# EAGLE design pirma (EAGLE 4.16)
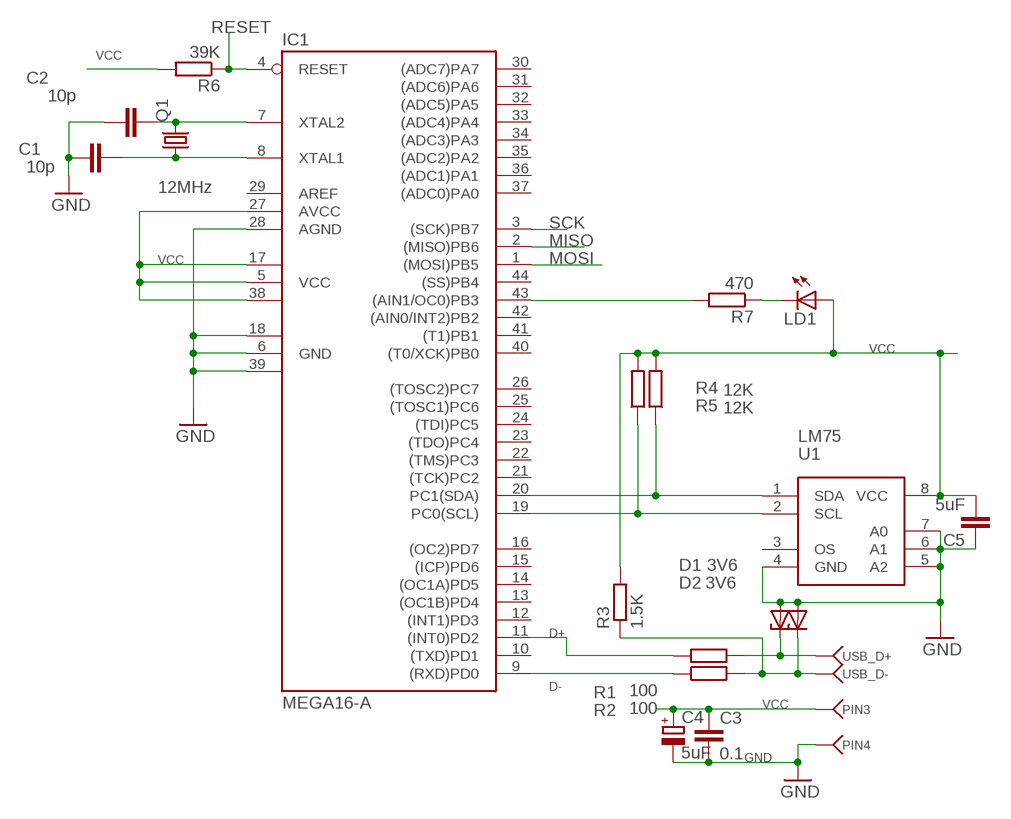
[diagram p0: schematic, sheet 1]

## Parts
C1  10p  C-EUC0603K  [C0603K]
C2  10p  C-EUC0603K  [C0603K]
C3  0.1  C-EUC3225  [C3225]
C4  5uF  CPOL-EUB/3528-21R  [B/3528-21R]
C5  5uF  C-EUC0603K  [C0603K]
D1  3V6  ZENER-DIODESOD80C  [SOD80C]
D2  3V6  ZENER-DIODESOD80C  [SOD80C]
IC1  MEGA16-A  [TQFP44]
LD1  LEDCHIPLED_1206  [CHIPLED_1206]
PIN3  PINSMD  [PIN-T]
PIN4  PINSMD  [PIN-T]
Q1  12MHz  CRYTALHC49S  [HC49/S]
R1  100  R-EU_M0805  [M0805]
R2  100  R-EU_M0805  [M0805]
R3  1.5K  R-EU_M0805  [M0805]
R4  12K  R-EU_M0805  [M0805]
R5  12K  R-EU_M0805  [M0805]
R6  39K  R-EU_M0805  [M0805]
R7  470  R-EU_M0805  [M0805]
U1  LM75  [SO08]
USB_D+  PINSMD  [PIN-T]
USB_D-  PINSMD  [PIN-T]

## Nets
D+: D1.C R1.2 USB_D+.P$1(P)
D-: D2.C R2.2 R3.1 USB_D-.P$1(P)
GND: C1.1 C2.1 C3.2 C4.- C5.1 D1.A D2.A IC1.6(GND) IC1.18(GND1) IC1.28(AGND) IC1.39(GND2) PIN4.P$1(P) U1.4(GND) U1.5(A2) U1.6(A1) U1.7(A0)
MISO: IC1.2((MISO)PB6)
MOSI: IC1.1((MOSI)PB5)
N$1: IC1.9((RXD)PD0) R2.1
N$2: IC1.11((INT0)PD2) R1.1
N$3: C2.2 IC1.7(XTAL2) Q1.2
N$4: C1.2 IC1.8(XTAL1) Q1.1
N$7: IC1.20(PC1(SDA)) R5.1 U1.1(SDA)
N$8: IC1.19(PC0(SCL)) R4.1 U1.2(SCL)
N$10: IC1.43((AIN1/OC0)PB3) R7.2
N$11: LD1.C R7.1
RESET: IC1.4(RESET) R6.1
SCK: IC1.3((SCK)PB7)
VCC: C3.1 C4.+ C5.2 IC1.5(VCC) IC1.17(VCC1) IC1.27(AVCC) IC1.38(VCC2) LD1.A PIN3.P$1(P) R3.2 R4.2 R5.2 R6.2 U1.8(VCC)
Unconnected: IC1.10((TXD)PD1) IC1.12((INT1)PD3) IC1.13((OC1B)PD4) IC1.14((OC1A)PD5) IC1.15((ICP)PD6) IC1.16((OC2)PD7) IC1.21((TCK)PC2) IC1.22((TMS)PC3) IC1.23((TDO)PC4) IC1.24((TDI)PC5) IC1.25((TOSC1)PC6) IC1.26((TOSC2)PC7) IC1.30((ADC7)PA7) IC1.31((ADC6)PA6) IC1.32((ADC5)PA5) IC1.33((ADC4)PA4) IC1.34((ADC3)PA3) IC1.35((ADC2)PA2) IC1.36((ADC1)PA1) IC1.37((ADC0)PA0) IC1.40((T0/XCK)PB0) IC1.41((T1)PB1) IC1.42((AIN0/INT2)PB2) IC1.44((SS)PB4) U1.3(OS)

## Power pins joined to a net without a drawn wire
AREF: IC1.29(AREF)

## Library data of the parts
C1-C3 C5 = rcl:C-EU: CAPACITOR, European symbol
C4 = rcl:CPOL-EU: POLARIZED CAPACITOR, European symbol
D1 D2 = diode:ZENER-DIODE: Z-Diode
IC1 = atmel:MEGA16: MICROCONTROLLER 16 Kbytes FLASH 1 kbytes SRAM 512 bytes EEPROM USART 8-channel 10 bit ADC Source: avr.lbr
LD1 = led:LED: LED
PIN3 PIN4 USB_D+ USB_D- = LevoROMS:PIN*: PIN
Q1 = crystal:CRYTAL: CRYSTAL
R1-R7 = rcl:R-EU_: RESISTOR, European symbol
U1 = LevoROMS:LM75

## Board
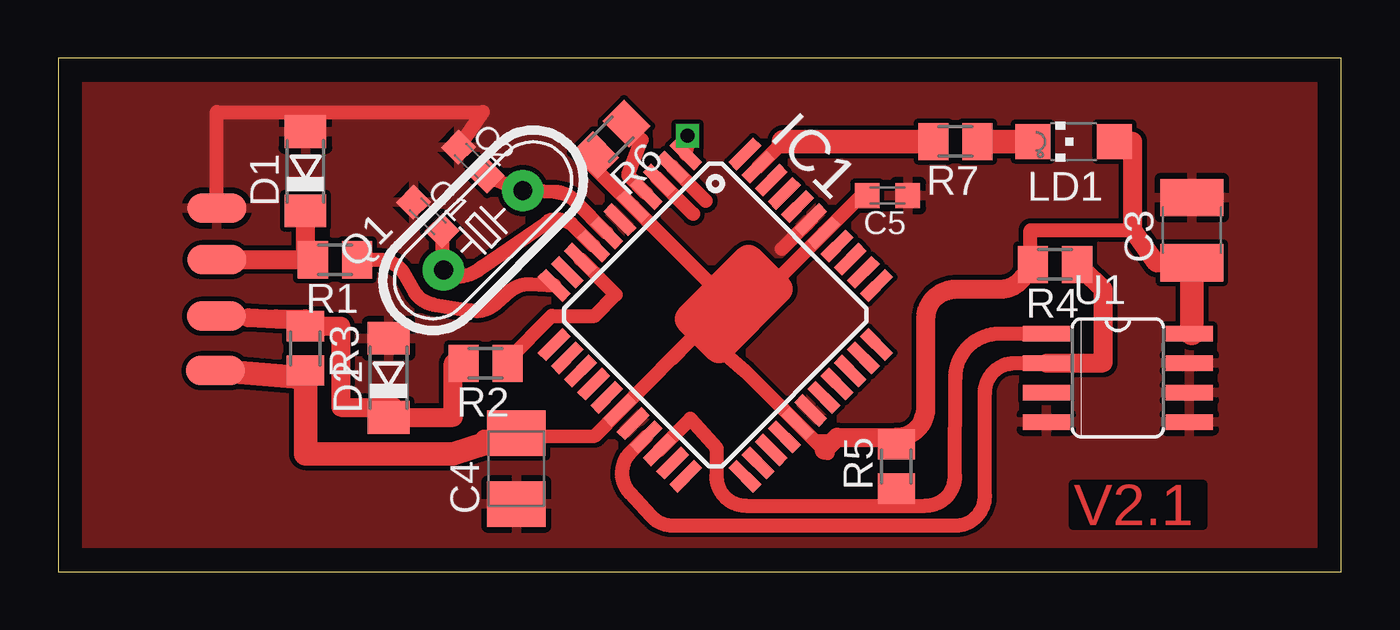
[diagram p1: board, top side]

Size 55.16 x 22.08 mm. Coordinates in mm from the lower left corner, seen from the top.
Outline: 0,0 55.16,0 55.16,22.08 0,22.08 0,0
Copper layers (1*16): Top 0.035mm / dielectric 1.5mm / Bottom 0.035mm
Design rules "default": minimum track width 10mil, minimum drill 24mil, track to track 8mil, track to pad 8mil, pad to pad 8mil, via to via 8mil, smd to smd 8mil, copper to edge 40mil, drill to drill 8mil, minimum pad ring 10mil, minimum via ring 8mil, stop-mask expansion 4mil, vias tented up to drill 0mil, thermal gap 10mil

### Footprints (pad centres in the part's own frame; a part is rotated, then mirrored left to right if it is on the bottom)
C0603K = smd 1.05 x 1.08: 1 -0.875,0; 2 0.875,0
C3225 = smd 1.6 x 2.7: 1 -1.4,0; 2 1.4,0
B/3528-21R = smd 1.95 x 2.5: + 1.525,0; - -1.525,0
SOD80C = smd 1.4 x 1.8: A 1.7,0; C -1.7,0
TQFP44 = smd 1.5 x 0.5: 1 -5.8,4; 2 -5.8,3.2; 3 -5.8,2.4; 4 -5.8,1.6; 5 -5.8,0.8; 6 -5.8,0; 7 -5.8,-0.8; 8 -5.8,-1.6; 9 -5.8,-2.4; 10 -5.8,-3.2; 11 -5.8,-4; 23 5.8,-4; 24 5.8,-3.2; 25 5.8,-2.4; 26 5.8,-1.6; 27 5.8,-0.8; 28 5.8,0; 29 5.8,0.8; 30 5.8,1.6; 31 5.8,2.4; 32 5.8,3.2; 33 5.8,4 | smd 0.5 x 1.5: 12 -4,-5.8; 13 -3.2,-5.8; 14 -2.4,-5.8; 15 -1.6,-5.8; 16 -0.8,-5.8; 17 0,-5.8; 18 0.8,-5.8; 19 1.6,-5.8; 20 2.4,-5.8; 21 3.2,-5.8; 22 4,-5.8; 34 4,5.8; 35 3.2,5.8; 36 2.4,5.8; 37 1.6,5.8; 38 0.8,5.8; 39 0,5.8; 40 -0.8,5.8; 41 -1.6,5.8; 42 -2.4,5.8; 43 -3.2,5.8; 44 -4,5.8
CHIPLED_1206 = smd 1.5 x 1.5: A 0,-1.75; C 0,1.75
PIN-T = smd 2.54 x 1.27: P$1 0,0
HC49/S = drill 0.813 pad 1.778 round: 1 -2.413,0; 2 2.413,0
M0805 = smd 1.3 x 1.6: 1 -0.95,0; 2 0.95,0
SO08 = smd 0.66 x 2.032: 1 -1.905,-3.073; 2 -0.635,-3.073; 3 0.635,-3.073; 4 1.905,-3.073; 5 1.905,3.073; 6 0.635,3.073; 7 -0.635,3.073; 8 -1.905,3.073

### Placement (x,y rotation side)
C1  15.89,15.27 315 top
C2  17.83,17.63 315 top
C3  48.73,14.68 90 top
C4  19.7,4.43 90 top
C5  35.65,16.17 180 top
D1  10.63,17.22 90 top
D2  14.21,8.33 90 top
IC1  28.25,11.03 315 top
LD1  43.65,18.49 90 top
PIN3  6.77,8.64 0 top
PIN4  6.82,15.63 0 top
Q1  18.27,14.68 45 top
R1  11.9,13.41 180 top
R2  18.37,8.95 180 top
R3  10.63,9.6 270 top
R4  42.85,13.21 180 top
R5  36.03,4.52 90 top
R6  23.76,18.59 225 top
R7  38.57,18.49 180 top
U1  45.55,8.33 270 top
USB_D+  6.82,13.41 0 top
USB_D-  6.8,10.99 0 top

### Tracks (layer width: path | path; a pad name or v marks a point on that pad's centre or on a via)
D+
  Top 0.61: R1.2 10.63,13.41
  Top 0.813: USB_D+.P$1 R1.2 | 10.63,13.41 D1.C
D-
  Top 0.61: USB_D-.P$1 8.18,10.92 | 10.63,10.87 R3.1
  Top 0.813: 8.18,10.92 9.36,10.87 10.63,10.87 | R3.1 12.15,10.55 12.15,7.06 14.44,7.06 14.44,6.63 D2.C 16.98,6.63 16.98,8.95 R2.2
GND
  Top 0.61: C2.1 18.25,19.76 6.82,19.76 PIN4.P$1 | 31.11,13.87 32.19,14.96 32.37,15.16 IC1.39
  pour Top: -2.07,23.57 -2.07,-0.56 57.62,-0.56 57.62,23.57
MISO
  Top 0.305: IC1.2 26.4,17.41 26.39,17.42
  Top 0.61: 27.85,15.94 26.39,17.42
MOSI  (via drill 0.6)
  Top 0.61: v27.05,18.74 27.14,18.49 IC1.1
N$1
  Top 0.61: IC1.9 23.97,11.91 23.07,11 21.22,11 19.38,9.14 R2.1
N$2
  Top 0.61: IC1.11 20.32,12.36 arc45 19.4,12.05 18.82,11.53 arc-53 17.72,11.23 16.1,11.49 arc-42 15.33,11.99 14.82,12.89 arc54 13.8,13.41 R1.1 13.17,13.41
N$3
  Top 0.61: IC1.7 22.19,15.96 arc43 21.35,16.33 19.95,16.4 Q1.2 19.94,16.38 C2.2
N$4
  Top 0.254: 20.99,14.99 21.13,15.1 arc-45 20.99,14.96 20.99,14.99 | 21.1,15.07 arc47 20.99,15.23 20.99,14.99
  Top 0.61: 16.58,13.01 16.77,12.78 17,12.69 arc45 18.2,13.08 20.99,14.99 | Q1.1 16.58,13.01 | 16.58,13.01 C1.2 | IC1.8 22.05,14.97 arc41 21.17,15.12 arc4 21.1,15.07
N$7
  Top 0.305: 36.03,2.83 R5.1
  Top 0.61: IC1.20 27.18,6.57 28.31,5.3 28.29,5.28 28.29,4.1 arc90 29.56,2.83 36.03,2.83 37.29,2.83 arc90 38.56,4.11 38.57,8.33 | 38.57,8.33 38.56,8.34 | 38.57,8.33 arc-90 40.48,10.24 U1.1
N$8
  Top 0.61: IC1.19 24.62,5.14 arc88 24.58,3.38 25.49,2.39 arc47 26.43,1.98 38.57,1.98 arc90 39.84,3.25 39.84,7.69 arc-90 41.11,8.96 U1.2
  Top 0.813: R4.1 44.92,12.14 44.92,9.6 44.92,8.98 U1.2
N$10
  Top 0.61: IC1.43 31.18,18.49
  Top 1.016: 31.18,18.49 R7.2
N$11
  Top 1.016: R7.1 LD1.C
RESET
  Top 0.61: IC1.4 24.51,17.04 25.08,18.56 24.44,19.2 R6.1
SCK
  Top 0.305: IC1.3 25.73,16.93
  Top 0.61: 25.73,16.93 27.29,15.37
VCC
  Top 0.254: R4.2 42.38,13.41 | C5.2 34.76,15.95 | 32.93,5.23 33.49,5.79 32.22,5.79 32.29,5.86 | 30.95,12.14 30.66,12.32
  Top 0.61: 26.41,9.17 27.68,10.46 IC1.17 23.07,5.84 18.25,5.79 C4.+ | 28.41,9.6 29.52,8.62 IC1.27 32.29,5.86 33.07,5.09 | 30.66,12.32 30.51,12.1 | 48.73,10.23 U1.8 | 28.45,11.97 28.34,12.07 IC1.5 22.79,17.61 R6.2 | 30.49,12.11 30.73,12.36 IC1.38 34.53,16.17 C5.2 | R4.2 41.8,13.27 41.8,14.68 45.96,14.68 46.19,14.68
  Top 0.813: R4.2 41.49,12.65 arc-53 40.47,12.14 38.57,12.14 arc45 37.67,11.77 arc45 37.3,10.87 37.3,7.04 arc-89 36.05,5.77 | C3.1 47.22,13.27 46.19,14.68 46.19,18.49 LD1.A | 36.05,5.77 36.03,5.79 R5.2 | 36.05,5.77 33.49,5.77 33.49,5.79 32.98,5.28 32.93,5.23
  Top 1.016: C4.+ 16.98,5.07 10.63,5.07 | PIN3.P$1 10.63,8.33 10.63,5.07 | C3.1 48.73,10.23 | 10.63,5.07 R3.2
  Top 1.27: 30.73,12.36 30.95,12.14 28.41,9.6 | 30.73,12.36 29.68,13.41 28.41,12.14 28.34,12.07 27.14,10.87 28.41,9.6 | 30.73,12.36 | 28.41,9.6 29.68,12.14 27.69,10.46 27.68,10.46

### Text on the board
Top: V2.1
